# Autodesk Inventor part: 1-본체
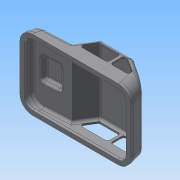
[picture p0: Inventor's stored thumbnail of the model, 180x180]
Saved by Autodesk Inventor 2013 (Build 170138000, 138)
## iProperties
Created: 2015-05
Part Number: 1-본체
Material: 일반
Document SubType Name: Modeling
Designer: Administrator
Density: 1 g/cm^3
Author: Administrator
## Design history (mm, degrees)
sketch "스케치1"
  geometry: L1 (0, 0)-(122, 0); L2 (0, 0)-(2.144, 8); L3 (2.144, 8)-(44.144, 10.201); L4 (44.144, 10.201)-(56.515, 30); L5 (56.515, 30)-(92, 30); L6 (92, 30)-(118.738, 12.175); L7 (118.738, 12.175)-(122, 0); L8 (118.738, 12.175)-(122, 10); L9 (122, 0)-(122, 25.67); L10 (0, 0)-(0, 17.193); L11 (0, 17.193)-(3.825, 17.193); L12 (3.825, 17.193)-(3.825, 0)
  constraints: 24 end point, 4 point on line, 3 perpendicular, 2 parallel, 1 collinear, 1 horizontal
  dimensions: "d0" = 122 distance of L1.start L1.end; "d2" = 105 deg angle of L1 L2; "d3" = 3 deg angle of L1 L3; "d4" = 125 deg angle of L4 L3; "d5" = 105 deg angle of L1 L7; "d6" = 20 vertical distance of L5.end L8.end; "d9" = 30 horizontal distance of L8.end L5.end; "d10" = 42 horizontal distance of L3.end L2.end; "d11" = 30 horizontal distance of L1.end L5.end; "d12" = 118.17486 distance between parallel lines of L12 L9; "d15" = 6.64394 distance from line of L9.end L7; "d16" = 8 distance from line of L1 L2.end
extrude "돌출1" new body sketch "스케치1" distance "d17" = 76; taper "d18" = 0 deg
fillet "모깎기1" dims "d19" = 12
fillet "모깎기2" dims "d20" = 3
sketch "스케치2"
  geometry: L1 (-12.423, 12)-(-12.423, 64) reference; L2 (0, 0)-(97.153, 0) reference; L3 (109.577, 12)-(109.577, 64) reference; L4 (0, 76)-(97.153, 76) reference; L5 (108.577, 64)-(108.577, 12); L6 (97.153, 1)-(0, 1); L7 (-11.423, 12)-(-11.423, 64); L8 (0, 75)-(97.153, 75); L9 (109.577, 64)-(109.577, 12); L10 (97.153, 0)-(0, 0); L11 (-12.423, 12)-(-12.423, 64); L12 (0, 76)-(97.153, 76); 5 further points; 4 other entities
  constraints: 16 end point, 14 equal length, 1 collinear, 28 other
  dimensions: "d21" = 1 distance between parallel lines of L4 L8
extrude "돌출2" join sketch "스케치2" distance "d22" = 1; taper "d23" = 0 deg
sketch "스케치3"
  geometry: L1 (-33.617, 48)-(-11.617, 48); L2 (-11.617, 48)-(-11.617, 22); L3 (-11.617, 22)-(-33.617, 22); L4 (-33.617, 22)-(-33.617, 48); L5 (-33.617, 48)-(-11.617, 22); L6 (-11.617, 48)-(-33.617, 22); L7 (-44.617, 61)-(-44.617, 9) reference; 4 further points
  constraints: 12 end point, 4 midpoint, 2 parallel, 1 horizontal, 1 horizontal alignment, 1 perpendicular
  dimensions: "d24" = 22 distance of L1.start L1.end; "d26" = 26 distance of L1.end L2.end; "d27" = 11 distance between parallel lines of L4 L7
extrude "돌출3" join sketch "스케치3" distance "d28" = 5; taper "d29" = -20 deg
fillet "모깎기3" dims "d30" = 3
feature "쉘1" dims "d31" = 2
sketch "스케치4"
  geometry: L1 (45.86, 7.287)-(58.178, 27) reference; L2 (109.577, 0)-(109.577, -3) reference; L3 (79.805, 27)-(59.841, 27); L4 (57.297, 25.59)-(51.673, 16.59); L5 (54.217, 12)-(79.805, 12); L6 (82.805, 15)-(82.805, 24); L7 (91.092, 32)-(58.178, 32) reference; L8 (53.938, 29.65)-(42.999, 12.144) reference; A1 r 5 centre (58.178, 27) between (58.178, 32) and (53.938, 29.65) reference; A2 r 3 centre (54.217, 15) between (51.673, 16.59) and (54.217, 12); A3 r 3 centre (79.805, 15) between (79.805, 12) and (82.805, 15); A4 r 3 centre (79.805, 24) between (82.805, 24) and (79.805, 27); A5 r 3 centre (59.841, 24) between (59.841, 27) and (57.297, 25.59); 4 further points
  constraints: 8 end point, 8 point on circle, 8 tangent, 6 point on line, 4 centre point, 2 equal radius, 2 perpendicular, 1 collinear, 1 parallel
  dimensions: "d32" = 15 vertical distance of point (48.805, 12) point (58.178, 27); "d34" = 34 distance of point (48.805, 12) point (82.805, 12); "d35" = 5 distance between parallel lines of L7 L3; "d37" = 5 distance between parallel lines of L8 L4; "d38" = 3 radius of A2; "d39" = 3 radius of A5
extrude "돌출4" cut sketch "스케치4" stored distance "d40" = 5; taper "d41" = 0 deg
sketch "스케치5"
  geometry: L1 (79.805, 12)-(54.217, 12) reference; L2 (85.592, 24.475)-(85.592, 15); L3 (88.592, 12)-(103.36, 12); L4 (104.98, 17.525)-(90.212, 27); L5 (91.092, 32)-(58.178, 32) reference; L6 (107.562, 22.029)-(118.906, 14.466) reference; A1 r 3 centre (103.36, 15) between (103.36, 12) and (104.98, 17.525); A2 r 3 centre (88.592, 15) between (85.592, 15) and (88.592, 12); A3 r 3 centre (88.592, 24.475) between (90.212, 27) and (85.592, 24.475); 4 further points
  constraints: 6 end point, 6 point on circle, 6 point on line, 6 tangent, 3 centre point, 2 equal radius, 2 perpendicular, 1 collinear
  dimensions: "d42" = 28 distance of point (85.592, 12) point (113.592, 12); "d45" = 5 distance from line of L6 point (113.592, 12); "d47" = 3 radius of A1; "d48" = 5 distance from line of L4.end L5
extrude "돌출5" cut sketch "스케치5" stored distance "d49" = 5; taper "d50" = 0 deg
sketch "스케치6"
  geometry: L1 (0, -6.366)-(0, 0) reference; A1 r 4 centre (5, -6.366) between (9, -6.366) and (1, -6.366); A2 r 4 centre (16, -6.366) between (20, -6.366) and (12, -6.366); A3 r 4 centre (36, -6.366) between (40, -6.366) and (32, -6.366); A4 r 4 centre (47, -6.366) between (51, -6.366) and (43, -6.366); 2 further points
  constraints: 8 point on circle, 4 centre point, 3 equal radius, 1 horizontal alignment, 13 other
  dimensions: "d51" = 4 radius of A1; "d53" = 11 distance of A2.centre A1.centre; "d54" = 11 distance of A4.centre A3.centre; "d55" = 20 distance of A2.centre A3.centre; "d56" = 5 distance from line of A1.centre L1
extrude "돌출6" join sketch "스케치6" distance "d57" = 2; taper "d58" = 0 deg
chamfer "모따기1" distance "d59" = 1; stored, may be unused: second distance "d60" = 2, angle "d61" = 45 deg
sketch "스케치9" dims "d0" = 122, "d2" = 105 deg, "d3" = 3 deg, "d4" = 125 deg, "d5" = 105 deg, "d6" = 20, "d9" = 30, "d10" = 42, "d11" = 30, "d12" = 118.17486, "d15" = 6.64394, "d16" = 8
  geometry: L1 (32.913, 0)-(32.913, -70) reference; L2 (65.822, -9)-(65.822, -61) reference; 3 further points
  constraints: 1 horizontal alignment, 1 midpoint, 1 other
  dimensions: "d62" = 50 distance from line of L2 point (15.822, -35)
feature "엠보싱1" sketch "스케치9" dims "d63" = 0.5, "d64" = 0
node "솔리드1"
